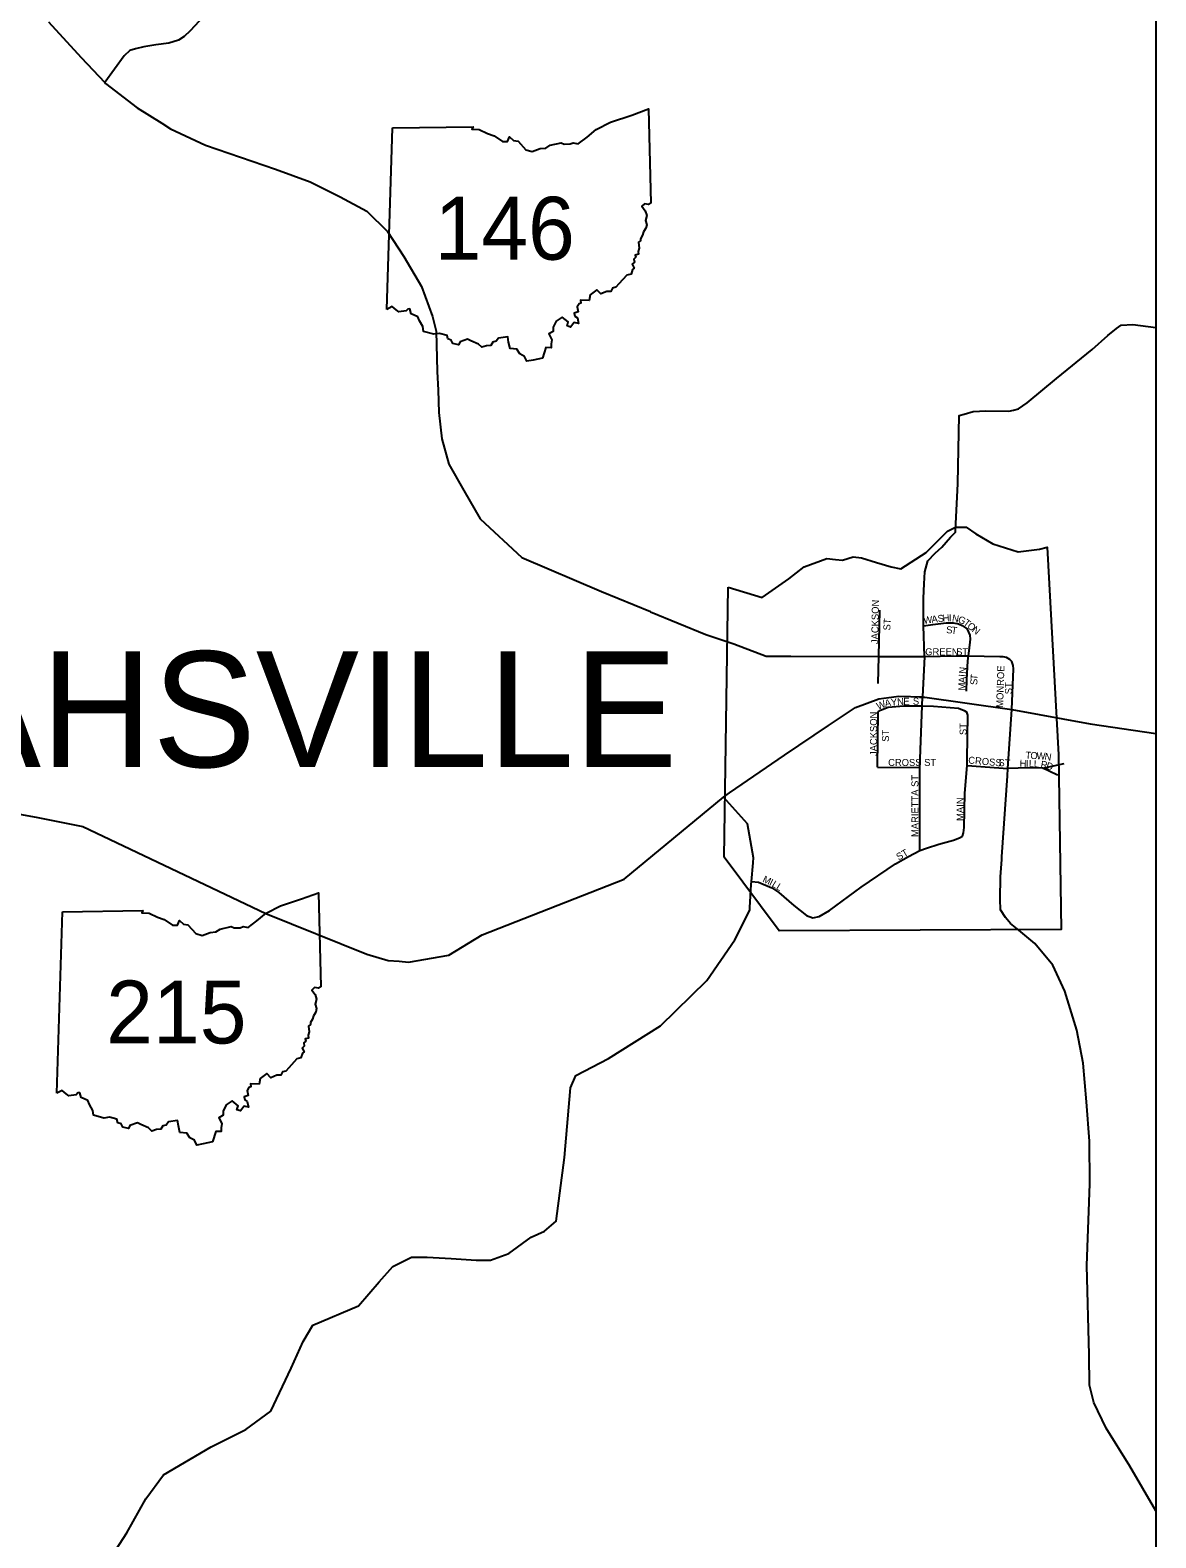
# Model space of a CAD drawing. Extents: x 0 to 34, y 0 to 22.
# Drawn here: x 29.182 to 30.697, y 11.131 to 13.16 of the extents above; entities that cross this region are included whole.
import ezdxf

# ---------------------------------------------------------------- set-up
doc = ezdxf.new("R2010")
doc.units = 0
for name, color, linetype in [('Default', 7, 'Continuous'), ('GM_X_City_Street', 7, 'Continuous'), ('GM_X_City_Street_Text', 7, 'Continuous'), ('GM_X_Corporation', 7, 'Continuous'), ('GM_X_State_Route', 7, 'Continuous'), ('GM_X_Unincorporated_Text', 7, 'Continuous')]:
    doc.layers.add(name, color=color, linetype=linetype)

msp = doc.modelspace()

# ---------------------------------------------------------------- linework, layer by layer
at = {"layer": 'Default'}
for p, q in [((30.697, 20.4625), (30.697, 9.6182)), ((29.6621, 12.7844), (29.6699, 13.0284)), ((29.218, 11.7298), (29.2258, 11.9738))]:
    msp.add_line(p, q, dxfattribs=at)
for points in [[(29.4328, 13.1971), (29.3975, 13.1589), (29.3896, 13.1513), (29.3817, 13.1467), (29.3688, 13.1425), (29.3514, 13.1404), (29.3352, 13.1377), (29.3238, 13.1349), (29.3163, 13.1326), (29.3088, 13.1257), (29.2825, 13.0895)], [(29.6699, 13.0284), (29.7781, 13.03), (29.7765, 13.027), (29.7866, 13.0264), (29.7975, 13.0212), (29.8067, 13.0179), (29.8178, 13.0102), (29.8246, 13.0102), (29.8274, 13.0166), (29.8325, 13.0117), (29.8387, 13.0108), (29.8492, 12.9991), (29.8579, 12.9966), (29.8684, 13.0006), (29.8761, 13.0013), (29.8818, 13.0052), (29.8967, 13.0086), (29.9009, 13.0066), (29.9087, 13.007), (29.9127, 13.0085), (29.9196, 13.0071), (29.9315, 13.0161), (29.944, 13.0265), (29.9631, 13.0364), (29.9916, 13.0457), (30.0142, 13.0541), (30.0175, 12.9274)], [(30.0175, 12.9274), (30.0142, 12.9256), (30.009, 12.9265), (30.0055, 12.923), (30.0098, 12.917), (30.0118, 12.9107), (30.01, 12.9039), (30.0118, 12.8982), (30.0106, 12.8934), (30.0074, 12.8886), (30.0062, 12.8841), (30.0034, 12.8794), (30.0036, 12.8767), (30.001, 12.8747), (30.0015, 12.8667), (30.0002, 12.8623), (30.0007, 12.8585), (29.9963, 12.8575), (29.9973, 12.8544), (29.9946, 12.852), (29.9952, 12.8478), (29.9921, 12.8451), (29.9951, 12.8398), (29.9927, 12.8382), (29.9907, 12.8317), (29.9851, 12.8304), (29.9742, 12.8186), (29.9703, 12.8141), (29.966, 12.813), (29.9635, 12.8084), (29.9582, 12.8084), (29.95, 12.8052), (29.9448, 12.8107), (29.9356, 12.8041), (29.9345, 12.7965), (29.9229, 12.7967), (29.9233, 12.7929), (29.9208, 12.7918), (29.9184, 12.7879), (29.9198, 12.781), (29.9143, 12.7793), (29.915, 12.7753), (29.9185, 12.773), (29.92, 12.7653), (29.9142, 12.7668), (29.9095, 12.7604), (29.9046, 12.762), (29.9062, 12.7674), (29.8979, 12.7739), (29.8901, 12.7687), (29.8861, 12.7603), (29.886, 12.7547), (29.8802, 12.7513), (29.884, 12.7434), (29.8832, 12.7379), (29.8834, 12.7327), (29.8761, 12.7329), (29.8717, 12.7189)], [(29.8717, 12.7189), (29.8591, 12.7162), (29.8504, 12.7146), (29.8472, 12.721), (29.841, 12.7244), (29.8369, 12.7307), (29.8279, 12.7316), (29.8257, 12.7404), (29.8248, 12.7475), (29.8124, 12.7458), (29.8091, 12.7414), (29.8047, 12.7402), (29.8022, 12.7358), (29.7962, 12.7355), (29.7898, 12.7334), (29.7856, 12.7377), (29.7752, 12.742), (29.7705, 12.7443), (29.7606, 12.7408), (29.7586, 12.7367), (29.7508, 12.7385), (29.7489, 12.7431), (29.7442, 12.7445), (29.7431, 12.7493), (29.733, 12.7519), (29.7252, 12.7509), (29.7116, 12.7548), (29.7107, 12.7612), (29.7061, 12.769), (29.7037, 12.7744), (29.6951, 12.7785), (29.6933, 12.7849), (29.6906, 12.7848), (29.688, 12.7822), (29.6784, 12.7809), (29.6746, 12.7836), (29.6692, 12.7881), (29.6621, 12.7844)], [(29.2258, 11.9738), (29.334, 11.9754), (29.3323, 11.9724), (29.3425, 11.9718), (29.3534, 11.9666), (29.3625, 11.9633), (29.3737, 11.9556), (29.3804, 11.9556), (29.3833, 11.962), (29.3884, 11.9571), (29.3945, 11.9562), (29.4051, 11.9445), (29.4138, 11.942), (29.4243, 11.946), (29.432, 11.9467), (29.4377, 11.9506), (29.4526, 11.954), (29.4568, 11.952), (29.4646, 11.9524), (29.4686, 11.9539), (29.4754, 11.9525), (29.4874, 11.9615), (29.4999, 11.9719), (29.519, 11.9818), (29.5475, 11.9911), (29.5701, 11.9995), (29.5734, 11.8728)], [(29.5734, 11.8728), (29.57, 11.871), (29.5649, 11.8719), (29.5614, 11.8684), (29.5657, 11.8624), (29.5677, 11.8561), (29.5659, 11.8493), (29.5677, 11.8436), (29.5665, 11.8388), (29.5633, 11.834), (29.5621, 11.8295), (29.5593, 11.8248), (29.5595, 11.8221), (29.5569, 11.8201), (29.5574, 11.8121), (29.5561, 11.8077), (29.5565, 11.8039), (29.5522, 11.8029), (29.5532, 11.7998), (29.5505, 11.7974), (29.5511, 11.7932), (29.548, 11.7905), (29.551, 11.7852), (29.5486, 11.7836), (29.5466, 11.7771), (29.541, 11.7758), (29.5301, 11.764), (29.5262, 11.7595), (29.5219, 11.7584), (29.5194, 11.7538), (29.5141, 11.7538), (29.5059, 11.7506), (29.5007, 11.7561), (29.4915, 11.7495), (29.4904, 11.7419), (29.4788, 11.7421), (29.4792, 11.7383), (29.4766, 11.7372), (29.4743, 11.7333), (29.4756, 11.7264), (29.4702, 11.7247), (29.4709, 11.7207), (29.4744, 11.7184), (29.4759, 11.7107), (29.4701, 11.7122), (29.4654, 11.7058), (29.4605, 11.7074), (29.4621, 11.7128), (29.4538, 11.7193), (29.446, 11.7141), (29.442, 11.7057), (29.4419, 11.7001), (29.4361, 11.6967), (29.4399, 11.6888), (29.4391, 11.6833), (29.4393, 11.6781), (29.432, 11.6783), (29.4275, 11.6643)], [(29.4275, 11.6643), (29.415, 11.6616), (29.4063, 11.66), (29.4031, 11.6664), (29.3969, 11.6698), (29.3928, 11.6761), (29.3838, 11.677), (29.3816, 11.6858), (29.3806, 11.6929), (29.3683, 11.6912), (29.365, 11.6868), (29.3606, 11.6856), (29.3581, 11.6812), (29.3521, 11.6809), (29.3457, 11.6788), (29.3415, 11.6831), (29.3311, 11.6874), (29.3264, 11.6897), (29.3165, 11.6862), (29.3144, 11.6821), (29.3067, 11.6839), (29.3048, 11.6885), (29.3001, 11.6899), (29.299, 11.6947), (29.2889, 11.6973), (29.2811, 11.6963), (29.2675, 11.7002), (29.2666, 11.7066), (29.262, 11.7144), (29.2596, 11.7198), (29.251, 11.7239), (29.2492, 11.7303), (29.2465, 11.7302), (29.2439, 11.7276), (29.2343, 11.7263), (29.2305, 11.729), (29.2251, 11.7335), (29.218, 11.7298)]]:
    msp.add_lwpolyline(points, dxfattribs=at)
at = {"layer": 'GM_X_City_Street'}
for points in [[(30.3233, 12.2811), (30.3242, 12.3174), (30.3257, 12.3797)], [(30.3842, 12.3584), (30.3967, 12.3604), (30.4148, 12.3627)], [(30.4148, 12.3627), (30.415, 12.3627), (30.416, 12.3628), (30.4244, 12.3626), (30.4314, 12.3614), (30.4365, 12.3592), (30.4433, 12.3539)], [(30.442, 12.2705), (30.4427, 12.2861), (30.444, 12.3115), (30.4449, 12.318), (30.4458, 12.3248), (30.4476, 12.3407), (30.4472, 12.346), (30.4433, 12.3539)], [(30.3857, 12.3173), (30.4284, 12.3182), (30.4449, 12.318), (30.4868, 12.3174), (30.491, 12.3171), (30.4955, 12.3164), (30.4999, 12.3139), (30.5031, 12.3107)], [(30.5032, 12.2458), (30.5055, 12.3005), (30.5048, 12.3053), (30.5031, 12.3107)], [(30.3792, 12.0562), (30.3795, 12.1165), (30.3794, 12.1681), (30.3826, 12.2507), (30.3831, 12.2628)], [(30.3223, 12.1685), (30.3232, 12.2428)], [(30.3232, 12.2428), (30.3263, 12.2451), (30.3368, 12.2489), (30.358, 12.251), (30.3826, 12.2507), (30.3978, 12.2505), (30.4312, 12.2477), (30.4392, 12.2447), (30.4426, 12.2425)], [(30.443, 12.1786), (30.4438, 12.2383), (30.4426, 12.2425)], [(30.437, 12.0756), (30.4382, 12.0799), (30.4392, 12.087), (30.44, 12.1332), (30.4429, 12.1706), (30.443, 12.1786)], [(30.5451, 12.1669), (30.5737, 12.1735)], [(30.3223, 12.1685), (30.3794, 12.1681)], [(30.4429, 12.1706), (30.4978, 12.1666)], [(30.566, 12.1574), (30.5636, 12.1579), (30.5451, 12.1669), (30.5254, 12.1676), (30.4978, 12.1666)], [(30.3883, 12.0593), (30.4049, 12.065), (30.4245, 12.0702), (30.4326, 12.0733), (30.437, 12.0756)], [(30.1528, 12.0144), (30.1622, 12.0138), (30.1804, 12.0062), (30.1897, 11.9996), (30.21, 11.9823), (30.2269, 11.969), (30.2354, 11.9658), (30.244, 11.9674), (30.258, 11.9755), (30.3005, 12.0068), (30.3468, 12.0382), (30.3639, 12.0481), (30.3792, 12.0562), (30.3883, 12.0593)]]:
    msp.add_lwpolyline(points, dxfattribs=at)
at = {"layer": 'GM_X_Corporation'}
msp.add_lwpolyline([(30.1214, 12.4106), (30.1672, 12.3967), (30.2029, 12.4216), (30.2235, 12.4381), (30.254, 12.449), (30.2661, 12.448), (30.2755, 12.447), (30.2895, 12.4513), (30.3008, 12.4499), (30.3209, 12.4437), (30.341, 12.4378), (30.3539, 12.4353), (30.3877, 12.4572), (30.4168, 12.4859), (30.4274, 12.4913), (30.4417, 12.4911), (30.4546, 12.4825), (30.4775, 12.4691), (30.5116, 12.4581), (30.5405, 12.4616), (30.5508, 12.4642), (30.5659, 12.1851), (30.5696, 11.9501), (30.1902, 11.9482), (30.1159, 12.0475)], close=True, dxfattribs=at)
at = {"layer": 'GM_X_State_Route'}
for points in [[(29.2067, 13.1712), (29.251, 13.1233), (29.2825, 13.0895), (29.2837, 13.0882), (29.3263, 13.0555), (29.3592, 13.0348), (29.3712, 13.0273), (29.418, 13.0053), (29.5121, 12.973), (29.559, 12.9559), (29.5994, 12.9357), (29.635, 12.9165), (29.663, 12.8892), (29.6852, 12.8555), (29.7089, 12.8152), (29.7235, 12.7749), (29.7284, 12.7552), (29.73, 12.7007), (29.7311, 12.6756), (29.7323, 12.6457), (29.7363, 12.6101), (29.7455, 12.5761), (29.7657, 12.5408), (29.7879, 12.5024), (29.844, 12.4506), (29.9512, 12.4048), (30.0168, 12.3777), (30.0169, 12.3776)], [(30.4273, 12.4864), (30.4273, 12.4867), (30.4303, 12.5499), (30.4325, 12.6417), (30.4389, 12.6433), (30.451, 12.6468), (30.4684, 12.6477), (30.4991, 12.6475), (30.5055, 12.6487), (30.5123, 12.6506), (30.5236, 12.6587), (30.5635, 12.6915), (30.6113, 12.7305), (30.6324, 12.7492), (30.644, 12.7588), (30.6504, 12.763), (30.6659, 12.7639), (30.697, 12.7598)], [(30.3857, 12.3173), (30.3842, 12.3584), (30.3841, 12.396), (30.385, 12.415), (30.3862, 12.4313), (30.3902, 12.4458), (30.3999, 12.4565), (30.4088, 12.4646), (30.4208, 12.4777), (30.4272, 12.4848), (30.4273, 12.4864)], [(30.0169, 12.3776), (30.0916, 12.3467), (30.1293, 12.3344), (30.1727, 12.3176), (30.2057, 12.3176)], [(30.2057, 12.3176), (30.2057, 12.3176), (30.3242, 12.3174), (30.3857, 12.3173)], [(30.3857, 12.3173), (30.3831, 12.2628), (30.5032, 12.2458)], [(30.1233, 12.1337), (30.1233, 12.1337), (30.1971, 12.1845), (30.2564, 12.2245), (30.2928, 12.2486), (30.3244, 12.2604), (30.3509, 12.2637), (30.3831, 12.2628)], [(30.4972, 12.1567), (30.4978, 12.1666), (30.5032, 12.2458)], [(30.5032, 12.2458), (30.6084, 12.2269), (30.697, 12.2137)], [(30.4898, 12.0479), (30.4972, 12.1567)], [(30.1354, 12.1056), (30.1353, 12.1057), (30.1151, 12.1281), (30.1233, 12.1337)], [(29.1608, 12.1063), (29.1926, 12.1008), (29.2529, 12.0884), (29.4992, 11.9716), (29.6353, 11.9167), (29.6638, 11.9082), (29.6786, 11.9072), (29.6915, 11.9058), (29.7455, 11.9153), (29.7904, 11.9426), (29.9816, 12.0178), (30.1151, 12.1281)], [(30.1551, 12.04), (30.1556, 12.0466), (30.1474, 12.0923), (30.1354, 12.1056)], [(30.1508, 11.9795), (30.1525, 12.0103), (30.1528, 12.0144), (30.155, 12.0395), (30.1551, 12.04)], [(30.697, 11.1678), (30.6619, 11.2281), (30.63, 11.279), (30.6136, 11.3137), (30.6079, 11.337), (30.6071, 11.3779), (30.6043, 11.4977), (30.6082, 11.6079), (30.6078, 11.6653), (30.6037, 11.7181), (30.599, 11.7702), (30.5908, 11.8145), (30.5746, 11.8671), (30.5584, 11.9019), (30.5343, 11.9313), (30.5126, 11.9489), (30.5014, 11.9579), (30.4946, 11.9661), (30.4878, 11.9766), (30.4873, 11.991), (30.488, 12.021), (30.4895, 12.0442), (30.4898, 12.0479)], [(29.2726, 11.0771), (29.3123, 11.1384), (29.3377, 11.1839), (29.3615, 11.2161), (29.4257, 11.2539), (29.4723, 11.277), (29.5061, 11.3017), (29.5332, 11.3598), (29.5497, 11.3957), (29.5627, 11.4175), (29.624, 11.4434), (29.6516, 11.4761), (29.6702, 11.4965), (29.6954, 11.509), (29.7163, 11.5089), (29.7489, 11.5072), (29.7823, 11.505), (29.8016, 11.505), (29.8261, 11.5141), (29.8565, 11.5358), (29.8741, 11.544), (29.8898, 11.5575), (29.9011, 11.6434), (29.9095, 11.7368), (29.9164, 11.7535), (29.9604, 11.7762), (30.0306, 11.8202), (30.0926, 11.8814), (30.1304, 11.9362), (30.1506, 11.976), (30.1508, 11.979), (30.1508, 11.9795)]]:
    msp.add_lwpolyline(points, dxfattribs=at)

# ---------------------------------------------------------------- texts
at = {"layer": 'Default'}
for s, p in [('146', (29.7263, 12.8512)), ('215', (29.2845, 11.7966))]:
    msp.add_text(s, height=0.08462, dxfattribs=at).set_placement(p)
at = {"layer": 'GM_X_City_Street_Text'}
for s, rotation, p in [('JACKSON', 89.0876, (30.3234, 12.3339)), ('ST', 86.4126, (30.3395, 12.3521)), ('W', 6.1489, (30.3848, 12.3613)), ('A', 6.1543, (30.3955, 12.3625)), ('S', 6.1461, (30.4038, 12.3634)), ('H', 3.7835, (30.4103, 12.3641)), ('S', 358.4422, (30.4148, 12.3485)), ('I', 359.5193, (30.4184, 12.3646)), ('T', 351.1126, (30.4212, 12.3484)), ('N', 350.7353, (30.4222, 12.3646)), ('G', 340.0785, (30.4299, 12.3634)), ('T', 322.7695, (30.4371, 12.3609)), ('O', 320.4323, (30.4423, 12.3569)), ('N', 320.2, (30.4487, 12.3517)), ('GREEN', 0, (30.3866, 12.3189)), ('ST', 0, (30.4282, 12.3189)), ('N', 84.4177, (30.4414, 12.2937)), ('T', 85.3498, (30.4569, 12.2854)), ('MONROE', 88.0919, (30.4914, 12.2482)), ('M', 89.4718, (30.4407, 12.2715)), ('A', 87.8797, (30.4408, 12.2814)), ('I', 85.2291, (30.4411, 12.2896)), ('S', 88.9618, (30.4568, 12.2789)), ('ST', 90, (30.5034, 12.2665)), ('W', 21.2644, (30.3233, 12.2455)), ('A', 11.73, (30.333, 12.2493)), ('Y', 5.0777, (30.3408, 12.2509)), ('N', 3.9595, (30.3491, 12.2516)), ('E', 1.202, (30.3572, 12.2522)), ('ST', 0, (30.37, 12.2524)), ('JACKSON', 90, (30.3218, 12.1834)), ('ST', 90, (30.3379, 12.2025)), ('ST', 90, (30.4423, 12.2116)), ('CROSS ST', 0, (30.3367, 12.17)), ('CROSS', 354.8033, (30.4442, 12.1734)), ('ST', 356.4254, (30.4849, 12.17)), ('H', 358.5794, (30.5136, 12.1689)), ('T', 356.5004, (30.5212, 12.18)), ('I', 358.557, (30.5219, 12.1687)), ('L', 358.569, (30.526, 12.1686)), ('O', 356.4796, (30.5279, 12.1796)), ('L', 357.5128, (30.5326, 12.1684)), ('W', 356.5027, (30.5362, 12.1791)), ('R', 349.8711, (30.5414, 12.1679)), ('N', 350.6922, (30.5467, 12.1785)), ('D', 341.3577, (30.5484, 12.1666)), ('MARIETTA ST', 90, (30.3775, 12.0744)), ('MAIN', 90, (30.4382, 12.096)), ('ST', 29.7432, (30.3509, 12.0426)), ('M', 334.16, (30.1669, 12.0144)), ('I', 334.1402, (30.1759, 12.01)), ('L', 328.0757, (30.1794, 12.0084)), ('L', 328.3644, (30.1851, 12.0048))]:
    msp.add_text(s, height=0.00945, rotation=rotation, dxfattribs=at).set_placement(p)
at = {"layer": 'GM_X_Unincorporated_Text'}
msp.add_text('SARAHSVILLE', height=0.155676, rotation=0, dxfattribs=at).set_placement((28.6298, 12.1685))

doc.saveas('drawing.dxf')
